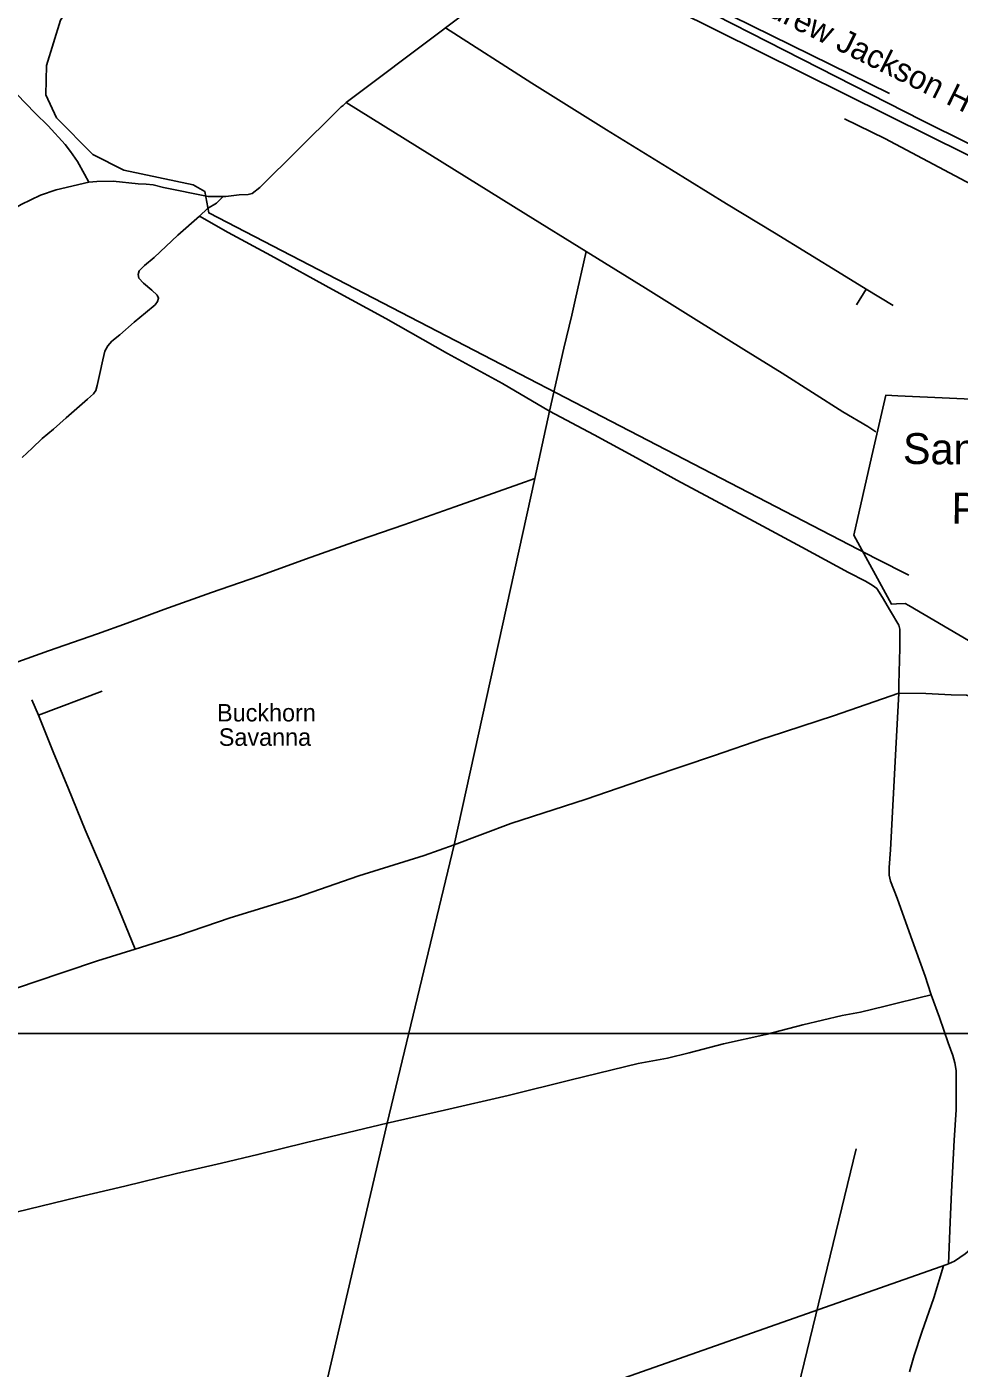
# Model space of a CAD drawing. Extents: x 2225501 to 2309677, y 165449 to 227696.
# Drawn here: x 2244504 to 2252503, y 188364 to 199877 of the extents above; entities that cross this region are included whole.
import ezdxf

# ---------------------------------------------------------------- set-up
doc = ezdxf.new("R2010")
doc.units = 0
for name, color, linetype in [('Collision Diagram Indicator Injury CELL', 7, 'Continuous'), ('Old_Level_3', 7, 'Continuous'), ('Old_Level_46', 7, 'Continuous'), ('P_HYD_Drop_Inlet_Box_Type_A_48_Dia-Bottom_CELL', 7, 'Continuous'), ('P_HYD_Endwall_838_01_48_Dia_Single_CELL', 7, 'Continuous'), ('P_HYD_Pipe_Pipe_Removal', 7, 'Continuous'), ('P_HYD_RipRap_Pad_876_02_36in_Outlet_With_Ditch-Top_CELL', 7, 'Continuous'), ('P_RDY_Concrete_Monolithic_Island', 7, 'Continuous'), ('Prop Support', 7, 'Continuous'), ('Scratch_Level_2', 7, 'Continuous')]:
    doc.layers.add(name, color=color, linetype=linetype)

msp = doc.modelspace()

# ---------------------------------------------------------------- linework, layer by layer
at = {"layer": 'Collision Diagram Indicator Injury CELL'}
msp.add_line((2250152, 200168), (2251905, 199306), dxfattribs=at)
at = {"layer": 'Old_Level_3'}
for p, q in [((2248095, 199869), (2248070, 199850)), ((2248070, 199850), (2247244, 199227)), ((2247244, 199227), (2248786, 198270)), ((2248786, 198270), (2249304, 197949)), ((2251705, 197626), (2251623, 197492)), ((2251705, 197626), (2251937, 197486)), ((2248862, 196001), (2248988, 196577)), ((2248171, 192857), (2248862, 196001)), ((2244603, 193969), (2245151, 194175)), ((2244546, 194100), (2244603, 193969)), ((2247595, 190467), (2248171, 192857)), ((2246857, 187307), (2247595, 190467))]:
    msp.add_line(p, q, dxfattribs=at)
for points in [[(2245035, 198545), (2245000, 198613), (2244939, 198721), (2244878, 198808), (2244832, 198868), (2244687, 199027), (2244576, 199135), (2244417, 199300), (2244316, 199393), (2244131, 199538), (2244008, 199623), (2243904, 199678), (2243868, 199706), (2243755, 199777), (2243516, 199963), (2243415, 200052), (2243234, 200226), (2243161, 200304), (2242901, 200547)], [(2248883, 200488), (2248861, 200452), (2248830, 200412), (2248198, 199947), (2248095, 199869)], [(2248095, 199869), (2248837, 199395), (2249477, 198993), (2250035, 198650), (2250506, 198359), (2250919, 198109), (2251495, 197754), (2251705, 197626)], [(2247244, 199227), (2247218, 199203), (2247200, 199191), (2247165, 199153), (2246502, 198499), (2246437, 198447), (2246403, 198439), (2246325, 198434), (2246211, 198421), (2246189, 198421)], [(2245035, 198545), (2244755, 198477), (2244622, 198432), (2244454, 198351), (2244357, 198296), (2244307, 198254), (2244254, 198215), (2244130, 198116), (2244011, 198015), (2243894, 197912), (2243795, 197806)], [(2246189, 198421), (2246059, 198422), (2245677, 198499), (2245587, 198520), (2245527, 198527), (2245460, 198531), (2245246, 198553), (2245105, 198550), (2245035, 198545)], [(2245986, 198253), (2246055, 198317), (2246131, 198363), (2246160, 198392), (2246189, 198421)], [(2245986, 198253), (2245799, 198090), (2245596, 197898), (2245514, 197828), (2245468, 197783), (2245459, 197751), (2245465, 197719), (2245506, 197678), (2245576, 197617), (2245622, 197573), (2245634, 197547), (2245625, 197521), (2245605, 197492), (2245523, 197422), (2245424, 197341), (2245302, 197233), (2245232, 197178), (2245200, 197140), (2245174, 197093), (2245157, 197018), (2245131, 196901), (2245107, 196800), (2245096, 196756), (2245075, 196727), (2245023, 196680), (2244933, 196602), (2244840, 196520), (2244732, 196424), (2244636, 196343), (2244549, 196261), (2244465, 196180)], [(2248988, 196577), (2248586, 196816), (2248114, 197072), (2247585, 197374), (2247126, 197624), (2246596, 197915), (2246230, 198113), (2245986, 198253)], [(2249304, 197949), (2249209, 197531), (2249179, 197403)], [(2249304, 197949), (2249811, 197634), (2250248, 197361), (2250655, 197108), (2250983, 196904), (2251504, 196573), (2251719, 196446), (2251789, 196402)], [(2249179, 197403), (2249111, 197118), (2248988, 196577)], [(2248988, 196577), (2249372, 196376), (2249734, 196177)], [(2249734, 196177), (2250082, 195986), (2250745, 195631), (2251152, 195410), (2251553, 195195), (2251699, 195119), (2251757, 195084), (2251798, 195055), (2251844, 194980), (2251914, 194863), (2251984, 194741), (2251995, 194706), (2251995, 194543), (2251984, 194235), (2251984, 194159)], [(2248862, 196001), (2248734, 195956), (2248175, 195758), (2247739, 195604), (2247355, 195470), (2246896, 195307), (2246495, 195162), (2246087, 195022), (2245680, 194876), (2245366, 194760), (2245110, 194667), (2244691, 194522), (2244168, 194335), (2243505, 194094), (2243336, 194033)], [(2251984, 194159), (2251425, 193964), (2250873, 193784), (2250826, 193768)], [(2251984, 194159), (2251961, 193679), (2251914, 192812), (2251902, 192661), (2251902, 192597), (2251914, 192545), (2251972, 192399), (2252089, 192068), (2252211, 191730), (2252259, 191577), (2252262, 191568)], [(2251984, 194159), (2252216, 194154), (2252434, 194144), (2252565, 194140), (2252666, 194106), (2252782, 194067), (2252826, 194038), (2252879, 194004)], [(2244603, 193969), (2244730, 193653), (2244861, 193336), (2245003, 192984), (2245146, 192652), (2245300, 192290), (2245434, 191961)], [(2250826, 193768), (2250396, 193621), (2249861, 193441), (2249302, 193249), (2248657, 193039), (2248171, 192857)], [(2248171, 192857), (2247912, 192764), (2247353, 192589), (2246818, 192403), (2246248, 192229), (2245806, 192077), (2245434, 191961)], [(2241371, 191218), (2241441, 191130), (2241499, 191026), (2241574, 190892), (2241621, 190810), (2241644, 190764), (2241679, 190746), (2241714, 190735), (2241784, 190741), (2241912, 190787), (2242208, 190886), (2242639, 191031), (2243063, 191171), (2243447, 191299), (2243889, 191447), (2244558, 191674), (2245111, 191861), (2245434, 191961)], [(2247595, 190467), (2248086, 190578), (2248633, 190706), (2249174, 190839), (2249750, 190979), (2250000, 191026), (2250186, 191072), (2250482, 191148), (2250843, 191229), (2251163, 191311), (2251500, 191392), (2251657, 191421), (2251867, 191472)], [(2251867, 191472), (2251948, 191491), (2252158, 191543), (2252262, 191568)], [(2252262, 191568), (2252333, 191374), (2252408, 191158), (2252449, 191048), (2252467, 190984), (2252478, 190920), (2252478, 190815), (2252478, 190617), (2252476, 190582)], [(2252476, 190582), (2252461, 190320), (2252438, 189878), (2252426, 189616), (2252411, 189261)], [(2240609, 188826), (2240804, 188868), (2241031, 188921), (2241409, 189005), (2241723, 189078), (2241993, 189142), (2242339, 189220), (2242802, 189328), (2243319, 189444), (2243933, 189587), (2244413, 189703), (2244942, 189831), (2245346, 189927), (2245789, 190035), (2246175, 190125), (2246487, 190198), (2246891, 190297), (2247333, 190404), (2247595, 190467)], [(2252411, 189261), (2252463, 189284), (2252555, 189346), (2253221, 189916)], [(2246857, 187307), (2252397, 189255), (2252411, 189261)], [(2252368, 189242), (2252286, 188968), (2252182, 188672), (2252118, 188474), (2252077, 188334)]]:
    msp.add_lwpolyline(points, dxfattribs=at)
at = {"layer": 'Old_Level_46'}
for points in [[(2256957, 196790), (2256925, 196796), (2256832, 196817), (2256652, 196876), (2256591, 196902), (2256480, 196951), (2256339, 197006), (2256283, 197031), (2254542, 197924), (2254210, 198073), (2253787, 198278), (2252186, 199074), (2250122, 200128), (2248769, 200789), (2247375, 201476), (2243675, 203271), (2243284, 203458), (2243017, 203588)], [(2242986, 203531), (2247394, 201341), (2248933, 200581), (2250062, 200025), (2252258, 198936), (2253668, 198238), (2254159, 197994), (2254221, 197964), (2255278, 197443), (2256251, 196964), (2256280, 196950), (2256416, 196885), (2256553, 196820), (2256635, 196788), (2256781, 196739), (2256906, 196710), (2256941, 196701), (2256960, 196697)]]:
    msp.add_lwpolyline(points, dxfattribs=at)
at = {"layer": 'P_HYD_Endwall_838_01_48_Dia_Single_CELL'}
msp.add_lwpolyline([(2253062, 194329), (2252072, 194910), (2252041, 194929), (2251966, 194925), (2251922, 194923), (2251600, 195513), (2251755, 196195), (2251874, 196716), (2251978, 196711), (2252864, 196669)], dxfattribs=at)
at = {"layer": 'P_HYD_Pipe_Pipe_Removal'}
msp.add_lwpolyline([(2243856, 191238), (2266254, 191238), (2266254, 223234), (2243856, 223234)], close=True, dxfattribs=at)
at = {"layer": 'P_HYD_RipRap_Pad_876_02_36in_Outlet_With_Ditch-Top_CELL'}
msp.add_lwpolyline([(2253062, 194329), (2252072, 194910), (2252041, 194929), (2251966, 194925), (2251922, 194923), (2251600, 195513), (2251755, 196195), (2251874, 196716), (2251978, 196711), (2252864, 196669)], dxfattribs=at)
at = {"layer": 'Prop Support'}
msp.add_line((2250476, 185539), (2251620, 190247), dxfattribs=at)
for points in [[(2252071, 195172), (2251795, 195311), (2246065, 198280), (2246030, 198464), (2245930, 198522), (2245337, 198648), (2245070, 198782), (2244758, 199096), (2244666, 199295), (2244672, 199544), (2244794, 199935), (2245286, 200673), (2245345, 200715)], [(2257977, 197228), (2257585, 197367), (2257284, 197432), (2256983, 197562), (2256581, 197793), (2256245, 198223), (2256077, 198361), (2255902, 198426), (2255660, 198424), (2255502, 198375), (2255014, 198004), (2254580, 198042), (2254397, 198006), (2254149, 197755), (2254041, 197764), (2251866, 198918), (2251520, 199088)]]:
    msp.add_lwpolyline(points, dxfattribs=at)

# ---------------------------------------------------------------- texts
at = {"layer": 'P_HYD_Drop_Inlet_Box_Type_A_48_Dia-Bottom_CELL'}
for s, p in [('Sandy Creek', (2252020, 196126)), ('Pop. 290', (2252436, 195614))]:
    msp.add_text(s, height=265, rotation=359.3894, dxfattribs=at).set_placement(p)
at = {"layer": 'P_RDY_Concrete_Monolithic_Island'}
for s, p in [('Buckhorn', (2246136, 193915)), ('Savanna', (2246151, 193706))]:
    msp.add_text(s, height=150, dxfattribs=at).set_placement(p)
at = {"layer": 'Scratch_Level_2'}
msp.add_text('Andrew Jackson Hwy.', height=200, rotation=333.7311, dxfattribs=at).set_placement((2250553, 200123))

doc.saveas('drawing.dxf')
